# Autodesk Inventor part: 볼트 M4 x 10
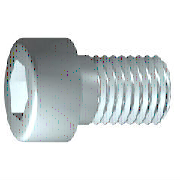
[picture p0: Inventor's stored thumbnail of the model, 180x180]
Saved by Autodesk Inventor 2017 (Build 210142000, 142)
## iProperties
IsCustomPart: 0
Created: 2016-04
Part Number: 볼트 M4 x 10
Material: 강철, 연강
Description: 6각머리 태핑 나사
Document SubType Name: Modeling
Standard: KS B 1003
Designer: mdu
Standards Organization: KS
Language: ko-KR
Size Designation: M 4 x 10
Categories: <MemberInstance><Categories><Category DisplayName="조임쇠" InternalName="e4da775c-781d-43d5-af7c-5136215cf5a6" Mnemonic="FSTN"><Category DisplayName="볼트" InternalN
Density: 7.86 g/cm^3
Mass: 2.0371 g
Surface Area: 3.0572 cm^2
Volume: 0.259174 cm^3
Appearance: 강철
Author: mdu
Revision Number: 1
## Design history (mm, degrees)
sketch "스케치1"
  geometry: L1 (-1, 0)-(10, 0); L2 (10, 0)-(10, 2); L3 (10, 2)-(1.75, 2); L4 (1.75, 2)-(1.32, 2); L5 (1.32, 2)-(0, 2); L6 (0, 2)-(0, 3.5); L7 (0, 3.5)-(-4, 3.5); L8 (-4, 3.5)-(-4, 1.732); L9 (-4, 1.732)-(-2, 1.732); L10 (-2, 1.732)-(-1, 0); L11 (-6.8, 0)-(12.8, 0) reference; L12 (0, -0.7)-(0, 4.2) reference; L13 (1.75, 2)-(0, 2)
  constraints: 22 end point, 6 parallel, 2 collinear, 2 perpendicular, 1 horizontal, 1 point on line
  dimensions: "d1" = 8.25 distance from line of L3.end L2 (= GEL); "d2" = 0.42952 distance of L4.end L3.end (computed from GAL); "d3" = 4 distance between parallel lines of L8 L6 (= KOH); "d4" = 2 distance of L8.end L9.end (= INTI); "d5" = 60 deg angle of L10 L1; "d6" = 4 diameter of L3 L1 (= GD); "d7" = 4 diameter of L5 L1 (= BDM); "d8" = 3.4641 diameter of L9 L1 (= 1.1547 x SW); "d9" = 7 diameter of L7 L1 (= KOD); "d26" = 10 distance between parallel lines of L12 L2 (= NLG)
revolve "본체" sketch "스케치1" stored, may be unused: angle "d10" = 90 deg
sketch "스케치2"
  geometry: L1 (0, -4.9)-(0, 4.9) reference; L2 (-4.9, 0)-(4.9, 0) reference; L3 (1.732, 0)-(0.866, -1.5); L4 (0.866, -1.5)-(-0.866, -1.5); L5 (-0.866, -1.5)-(-1.732, 0); L6 (-1.732, 0)-(-0.866, 1.5); L7 (-0.866, 1.5)-(0.866, 1.5); L8 (0.866, 1.5)-(1.732, 0); 2 further points
  constraints: 12 end point, 1 coincident, 1 horizontal alignment, 1 point on line, 12 other
extrude "슬롯" join sketch "스케치2" stored distance "d11" = 10; taper "d12" = 0 deg
workplane "Work Plane1"
fillet "Fillet2" dims "d30" = 0.1 (= R)
body "Solid1"
fillet "모깎기1" dims "d17" = 0.4 (= RR)
feature "스레드" dims "d13" = 8.25 (= GEL), "d14" = 0
chamfer "모따기1" distance "d15" = 0.42941 (= -0.5 x SPD + 0.5 x GD); stored, may be unused: second distance "d16" = 0.42941 (= GUL), angle "d27" = 45 deg
other parameters: "GD" = 4 (= NND) [user parameter; used in 2 equation terms], "NLG" = 10 [user parameter; used in 1 equation term], "GEL" = 8.25 [user parameter; used in 2 equation terms], "KOD" = 7 [user parameter; used in 1 equation term], "KOH" = 4 [user parameter; used in 1 equation term], "INTI" = 2 [user parameter; used in 1 equation term], "GAL" = 0.42941 (= 0.61345 x PTC) [user parameter; used in 1 equation term], "GUL" = 0.42941 (= 0.61345 x PTC) [user parameter; used in 1 equation term], "BDM" = 4 (= NND) [user parameter; used in 1 equation term], "SW" = 3 [user parameter; used in 2 equation terms], "RR" = 0.4 [user parameter; used in 1 equation term], "SPD" = 3.14117 (= NND - 1.2269 x PTC) [user parameter; used in 1 equation term], "d19" = 0, "d28" = 0, "d29" = 0, "R" = 0.1 [user parameter; used in 1 equation term], "PHH" = 0.2 [user parameter], "GD1" = 3.14117 (= THREADDIA - 1.2269 x PTC) [user parameter], "THREADDIA" = 4 [user parameter; used in 1 equation term], "FAWI" = 45 deg [user parameter], "TPU" = 14.28571 (computed from PTC) [user parameter], "PTC" = 0.7 [user parameter; used in 5 equation terms], "NND" = 4 [user parameter; used in 3 equation terms], "TOA" = 30 deg [user parameter], "E0" = 3.465 (= 1.155 x SW) [user parameter]
